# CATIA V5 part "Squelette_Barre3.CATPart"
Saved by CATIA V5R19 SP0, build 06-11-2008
Part number: Squelette_Barre3
Bounding box of the stored display mesh (mm): x 6 to 15, y 0 to 12, z 0 to 30
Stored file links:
  F:\IAO\Catia\Squelette_Barre3.CATPart
  F:\IAO\Catia\Etau.CATProduct
  F:\IAO\Catia\Squelette_barre4.CATPart
  F:\IAO\Catia\Base.CATPart
  F:\IAO\Catia\Squelette_pivot2.CATPart
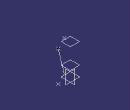
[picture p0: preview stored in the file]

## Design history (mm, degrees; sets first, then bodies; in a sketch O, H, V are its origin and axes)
Set1
  Plane1: linked copy from another document
  Point1: linked copy from another document
  Point2: linked copy from another document
Body1 (main body)
  Plane2: type Offset, Offset 10, RefPlane Plane1
  Point3: (0, 0, 15), relative to Point1
  Point4: (0, 0, 15), relative to Point2
  Line1: type PtPt, SecondPoint Point3, FirstPoint Point2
